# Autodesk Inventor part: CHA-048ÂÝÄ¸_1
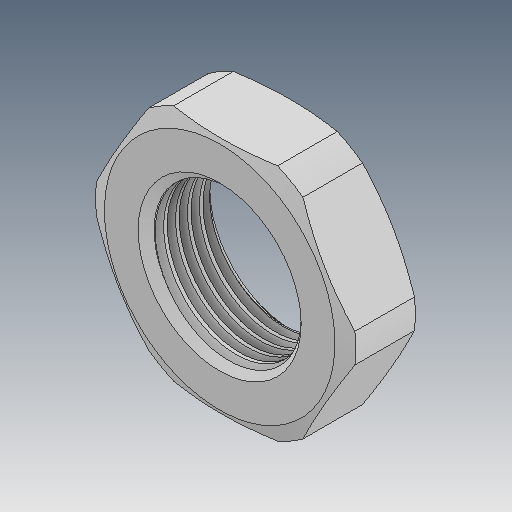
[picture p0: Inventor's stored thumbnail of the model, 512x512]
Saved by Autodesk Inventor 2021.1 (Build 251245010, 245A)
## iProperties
Created: 2019-12
Part Number: CHA-048ÂÝÄ¸_1
Material: Ogólny
Document SubType Name: Modeling
Designer: user
Density: 1 g/cm^3
Appearance: Domyślna
Author: user
Revision Number: ÈÎºÎ
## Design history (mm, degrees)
feature "ÊäÈë1"
node "Bryła1"
